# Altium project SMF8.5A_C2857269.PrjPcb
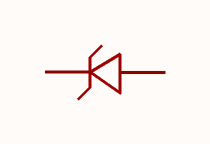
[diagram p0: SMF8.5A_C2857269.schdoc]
1 sheet, 1 parts. Net scope: global (net labels, ports and power ports of the same name join across sheets).

## Sheet SMF8.5A_C2857269.schdoc
size 127 x 101 mm

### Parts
D?  smf8.5a_c2857269  [SOD-123FL_L2.8-W1.8-LS3.6-RD]  (value not drawn)

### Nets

Not connected (* = marked no-connect by the designer): D? 1 2

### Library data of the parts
D? = smf8.5a_c2857269: 极性:单向;反向截止电压(Vrwm):8.5V;钳位电压:14.4V;峰值脉冲电流(Ipp):13.9A;峰值脉冲功率(Ppp):200W;击穿电压(VBR):10.4V;; Manufacturer: JSMSEMI(杰盛微); AddInBom: yes; ModelId: 9a6bf0a398604d2998ad78800a7c8ef9; ModelTransform: 141.732,70.866,0,0,0,0,0,0,0; Polarity: 单向; Reverse Stand-Off Voltage (Vrwm): 8.5V; Clamping Voltage: 14.4V; Peak Pulse Current (Ipp): 13.9A; Peak Pulse Power Dissipation (Ppp): 200W; Voltage - Breakdown: 10.4V; Reverse Leakage Current (Ir): 10uA; Number of Channels: 单路; Type: TVS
